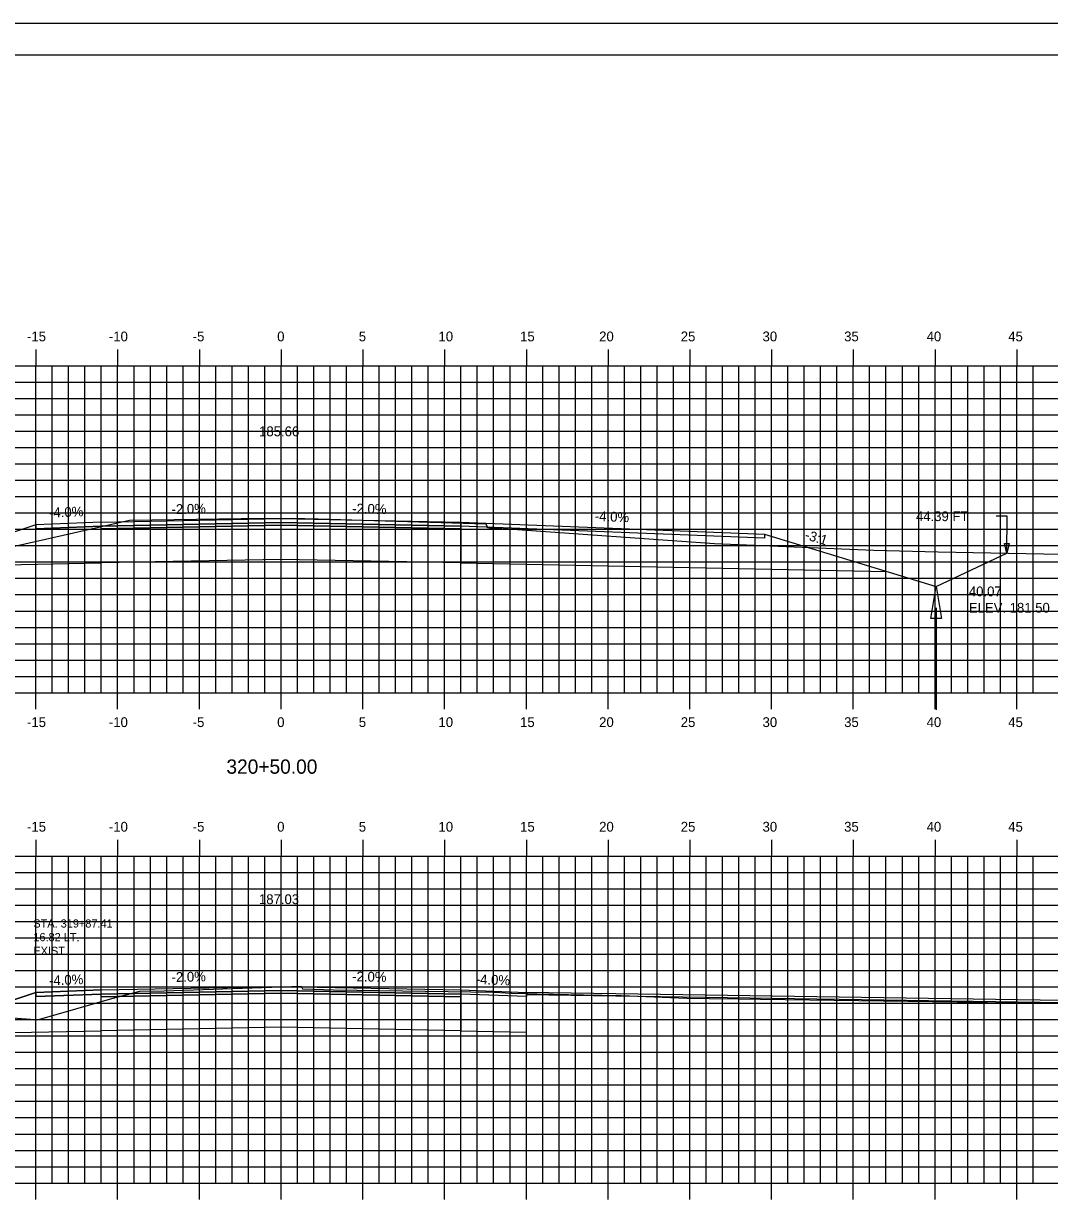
# Model space of a CAD drawing. Extents: x 1139650 to 1139820, y 608981 to 609091.
# Drawn here: x 1139717.5 to 1139780.2, y 609019.1 to 609091.3 of the extents above; entities that cross this region are included whole.
import ezdxf

# ---------------------------------------------------------------- set-up
doc = ezdxf.new("R2010")
doc.units = 0
for name, color, linetype in [('ANNOTATION', 7, 'Continuous'), ('BORDER', 7, 'Continuous'), ('D_Drainage_Ditch_Line', 7, 'Continuous'), ('D_Roadway_Centerline', 7, 'Continuous'), ('D_Roadway_Centerline_Text', 7, 'Continuous'), ('D_Roadway_Edge_Shoulder', 7, 'Continuous'), ('D_Roadway_Edge_TW', 7, 'Continuous'), ('D_Roadway_Pavement', 7, 'Continuous'), ('D_Roadway_SubGrade', 7, 'Continuous'), ('D_Text_Monospaced', 7, 'Continuous'), ('D_Text_Standard', 7, 'Continuous'), ('H_V ANNOTATION', 7, 'Continuous'), ('MAJOR', 7, 'Continuous'), ('MINOR', 7, 'Continuous'), ('PLOT BOUNDARY', 7, 'Continuous'), ('S_Roadway_Centerline', 7, 'Continuous')]:
    doc.layers.add(name, color=color, linetype=linetype)

msp = doc.modelspace()

# ---------------------------------------------------------------- linework, layer by layer
msp.add_lwpolyline([(1139697.827, 609032.096), (1139699.077, 609031.975), (1139700.327, 609031.71), (1139701.577, 609031.3), (1139702.827, 609030.747), (1139707.494, 609028.414), (1139710.494, 609029.414), (1139718.217, 609031.989), (1139718.218, 609031.989), (1139722.218, 609032.149), (1139733.218, 609032.369), (1139744.218, 609032.149), (1139748.218, 609031.989)])
at = {"layer": 'BORDER'}
msp.add_lwpolyline([(1139658.219, 608984.335), (1139818.219, 608984.335), (1139818.219, 609089.335), (1139658.219, 609089.335)], close=True, dxfattribs=at)
at = {"layer": 'D_Drainage_Ditch_Line'}
msp.add_line((1139773.288, 609055.523), (1139773.288, 609049.279), dxfattribs=at)
msp.add_lwpolyline([(1139773.616, 609054.867), (1139772.96, 609054.867), (1139773.288, 609056.835)], close=True, dxfattribs=at)
at = {"layer": 'D_Roadway_Edge_Shoulder'}
for points in [[(1139722.218, 609060.776), (1139718.218, 609060.616), (1139718.218, 609060.366), (1139722.218, 609060.526)], [(1139744.218, 609060.776), (1139762.791, 609060.033), (1139762.791, 609059.783), (1139744.218, 609060.526)], [(1139722.218, 609032.149), (1139718.218, 609031.989), (1139718.218, 609031.739), (1139722.218, 609031.899)], [(1139744.218, 609032.149), (1139748.218, 609031.989), (1139748.218, 609031.739), (1139744.218, 609031.899)]]:
    msp.add_lwpolyline(points, close=True, dxfattribs=at)
for points in [[(1139797.588, 609031.189), (1139790.588, 609031.365), (1139748.218, 609031.989)], [(1139748.218, 609031.989), (1139748.218, 609031.864), (1139790.588, 609031.24), (1139797.588, 609031.064), (1139797.588, 609031.189)]]:
    msp.add_lwpolyline(points, dxfattribs=at)
at = {"layer": 'D_Roadway_Edge_TW'}
for points in [[(1139722.218, 609060.526), (1139722.218, 609060.776), (1139733.218, 609060.996), (1139744.218, 609060.776), (1139744.218, 609060.526), (1139733.218, 609060.746)], [(1139722.218, 609031.899), (1139722.218, 609032.149), (1139733.218, 609032.369), (1139744.218, 609032.149), (1139744.218, 609031.899), (1139733.218, 609032.119)]]:
    msp.add_lwpolyline(points, close=True, dxfattribs=at)
at = {"layer": 'D_Roadway_Pavement'}
for points in [[(1139722.218, 609060.359), (1139722.218, 609060.526), (1139733.218, 609060.746), (1139744.218, 609060.526), (1139744.218, 609060.359), (1139733.218, 609060.579)], [(1139722.218, 609031.732), (1139722.218, 609031.899), (1139733.218, 609032.119), (1139744.218, 609031.899), (1139744.218, 609031.732), (1139733.218, 609031.952)]]:
    msp.add_lwpolyline(points, close=True, dxfattribs=at)
at = {"layer": 'D_Roadway_SubGrade'}
for p, q in [((1139762.791, 609060.033), (1139773.288, 609056.835)), ((1139773.288, 609056.835), (1139777.608, 609058.876))]:
    msp.add_line(p, q, dxfattribs=at)
for points in [[(1139722.218, 609060.359), (1139722.218, 609060.526), (1139718.218, 609060.366), (1139718.218, 609060.616), (1139718.217, 609060.616), (1139710.494, 609058.041), (1139722.218, 609058.276)], [(1139722.218, 609058.276), (1139722.218, 609060.359), (1139733.218, 609060.579), (1139744.218, 609060.359), (1139744.218, 609058.276), (1139733.218, 609058.496)], [(1139722.218, 609031.732), (1139722.218, 609031.899), (1139718.218, 609031.739), (1139718.218, 609031.989), (1139718.217, 609031.989), (1139710.494, 609029.414), (1139722.218, 609029.649)], [(1139748.218, 609030.989), (1139748.218, 609031.989), (1139748.218, 609031.989), (1139748.218, 609031.739), (1139744.218, 609031.899), (1139744.218, 609031.732), (1139744.218, 609029.649), (1139748.218, 609029.569)], [(1139722.218, 609029.649), (1139722.218, 609031.732), (1139733.218, 609031.952), (1139744.218, 609031.732), (1139744.218, 609029.649), (1139733.218, 609029.869)]]:
    msp.add_lwpolyline(points, close=True, dxfattribs=at)
msp.add_lwpolyline([(1139744.218, 609058.276), (1139754.218, 609058.076), (1139770.269, 609057.755)], dxfattribs=at)
at = {"layer": 'D_Text_Standard'}
msp.add_lwpolyline([(1139777.608, 609058.876), (1139777.629, 609061.135), (1139776.95, 609061.135)], dxfattribs=at)
msp.add_lwpolyline([(1139777.608, 609058.876), (1139777.468, 609059.46), (1139777.759, 609059.457)], close=True, dxfattribs=at)
at = {"layer": 'MAJOR'}
for p, q in [((1139718.218, 609071.337), (1139718.218, 609070.335)), ((1139723.218, 609071.337), (1139723.218, 609070.335)), ((1139728.218, 609071.337), (1139728.218, 609070.335)), ((1139733.218, 609071.337), (1139733.218, 609070.335)), ((1139738.218, 609071.337), (1139738.218, 609070.335)), ((1139743.218, 609071.337), (1139743.218, 609070.335)), ((1139748.218, 609071.337), (1139748.218, 609070.335)), ((1139753.218, 609071.337), (1139753.218, 609070.335)), ((1139758.218, 609071.337), (1139758.218, 609070.335)), ((1139763.218, 609071.337), (1139763.218, 609070.335)), ((1139768.218, 609071.337), (1139768.218, 609070.335)), ((1139773.218, 609071.337), (1139773.218, 609070.335)), ((1139778.218, 609071.337), (1139778.218, 609070.335)), ((1139663.218, 609070.335), (1139803.218, 609070.335)), ((1139663.218, 609070.335), (1139803.218, 609070.335)), ((1139718.218, 609050.335), (1139718.218, 609070.335)), ((1139723.218, 609050.335), (1139723.218, 609070.335)), ((1139728.218, 609050.335), (1139728.218, 609070.335)), ((1139733.218, 609050.335), (1139733.218, 609070.335)), ((1139738.218, 609050.335), (1139738.218, 609070.335)), ((1139743.218, 609050.335), (1139743.218, 609070.335)), ((1139748.218, 609050.335), (1139748.218, 609070.335)), ((1139753.218, 609050.335), (1139753.218, 609070.335)), ((1139758.218, 609050.335), (1139758.218, 609070.335)), ((1139763.218, 609050.335), (1139763.218, 609070.335)), ((1139768.218, 609050.335), (1139768.218, 609070.335)), ((1139773.218, 609050.335), (1139773.218, 609070.335)), ((1139778.218, 609050.335), (1139778.218, 609070.335)), ((1139663.218, 609065.335), (1139803.218, 609065.335)), ((1139663.218, 609060.335), (1139803.218, 609060.335)), ((1139663.218, 609055.335), (1139803.218, 609055.335)), ((1139663.218, 609050.335), (1139803.218, 609050.335)), ((1139663.218, 609050.335), (1139803.218, 609050.335)), ((1139718.218, 609049.333), (1139718.218, 609050.335)), ((1139723.218, 609049.333), (1139723.218, 609050.335)), ((1139728.218, 609049.333), (1139728.218, 609050.335)), ((1139733.218, 609049.333), (1139733.218, 609050.335)), ((1139738.218, 609049.333), (1139738.218, 609050.335)), ((1139743.218, 609049.333), (1139743.218, 609050.335)), ((1139748.218, 609049.333), (1139748.218, 609050.335)), ((1139753.218, 609049.333), (1139753.218, 609050.335)), ((1139758.218, 609049.333), (1139758.218, 609050.335)), ((1139763.218, 609049.333), (1139763.218, 609050.335)), ((1139768.218, 609049.333), (1139768.218, 609050.335)), ((1139773.218, 609049.333), (1139773.218, 609050.335)), ((1139778.218, 609049.333), (1139778.218, 609050.335)), ((1139718.218, 609041.337), (1139718.218, 609040.335)), ((1139723.218, 609041.337), (1139723.218, 609040.335)), ((1139728.218, 609041.337), (1139728.218, 609040.335)), ((1139733.218, 609041.337), (1139733.218, 609040.335)), ((1139738.218, 609041.337), (1139738.218, 609040.335)), ((1139743.218, 609041.337), (1139743.218, 609040.335)), ((1139748.218, 609041.337), (1139748.218, 609040.335)), ((1139753.218, 609041.337), (1139753.218, 609040.335)), ((1139758.218, 609041.337), (1139758.218, 609040.335)), ((1139763.218, 609041.337), (1139763.218, 609040.335)), ((1139768.218, 609041.337), (1139768.218, 609040.335)), ((1139773.218, 609041.337), (1139773.218, 609040.335)), ((1139778.218, 609041.337), (1139778.218, 609040.335)), ((1139663.218, 609040.335), (1139803.218, 609040.335)), ((1139663.218, 609040.335), (1139803.218, 609040.335)), ((1139718.218, 609020.335), (1139718.218, 609040.335)), ((1139723.218, 609020.335), (1139723.218, 609040.335)), ((1139728.218, 609020.335), (1139728.218, 609040.335)), ((1139733.218, 609020.335), (1139733.218, 609040.335)), ((1139738.218, 609020.335), (1139738.218, 609040.335)), ((1139743.218, 609020.335), (1139743.218, 609040.335)), ((1139748.218, 609020.335), (1139748.218, 609040.335)), ((1139753.218, 609020.335), (1139753.218, 609040.335)), ((1139758.218, 609020.335), (1139758.218, 609040.335)), ((1139763.218, 609020.335), (1139763.218, 609040.335)), ((1139768.218, 609020.335), (1139768.218, 609040.335)), ((1139773.218, 609020.335), (1139773.218, 609040.335)), ((1139778.218, 609020.335), (1139778.218, 609040.335)), ((1139663.218, 609035.335), (1139803.218, 609035.335)), ((1139663.218, 609030.335), (1139803.218, 609030.335)), ((1139663.218, 609025.335), (1139803.218, 609025.335)), ((1139663.218, 609020.335), (1139803.218, 609020.335)), ((1139663.218, 609020.335), (1139803.218, 609020.335)), ((1139718.218, 609019.333), (1139718.218, 609020.335)), ((1139723.218, 609019.333), (1139723.218, 609020.335)), ((1139728.218, 609019.333), (1139728.218, 609020.335)), ((1139733.218, 609019.333), (1139733.218, 609020.335)), ((1139738.218, 609019.333), (1139738.218, 609020.335)), ((1139743.218, 609019.333), (1139743.218, 609020.335)), ((1139748.218, 609019.333), (1139748.218, 609020.335)), ((1139753.218, 609019.333), (1139753.218, 609020.335)), ((1139758.218, 609019.333), (1139758.218, 609020.335)), ((1139763.218, 609019.333), (1139763.218, 609020.335)), ((1139768.218, 609019.333), (1139768.218, 609020.335)), ((1139773.218, 609019.333), (1139773.218, 609020.335)), ((1139778.218, 609019.333), (1139778.218, 609020.335))]:
    msp.add_line(p, q, dxfattribs=at)
at = {"layer": 'MINOR'}
for p, q in [((1139719.218, 609050.335), (1139719.218, 609070.335)), ((1139720.218, 609050.335), (1139720.218, 609070.335)), ((1139721.218, 609050.335), (1139721.218, 609070.335)), ((1139722.218, 609050.335), (1139722.218, 609070.335)), ((1139724.218, 609050.335), (1139724.218, 609070.335)), ((1139725.218, 609050.335), (1139725.218, 609070.335)), ((1139726.218, 609050.335), (1139726.218, 609070.335)), ((1139727.218, 609050.335), (1139727.218, 609070.335)), ((1139729.218, 609050.335), (1139729.218, 609070.335)), ((1139730.218, 609050.335), (1139730.218, 609070.335)), ((1139731.218, 609050.335), (1139731.218, 609070.335)), ((1139732.218, 609050.335), (1139732.218, 609070.335)), ((1139734.218, 609050.335), (1139734.218, 609070.335)), ((1139735.218, 609050.335), (1139735.218, 609070.335)), ((1139736.218, 609050.335), (1139736.218, 609070.335)), ((1139737.218, 609050.335), (1139737.218, 609070.335)), ((1139739.218, 609050.335), (1139739.218, 609070.335)), ((1139740.218, 609050.335), (1139740.218, 609070.335)), ((1139741.218, 609050.335), (1139741.218, 609070.335)), ((1139742.218, 609050.335), (1139742.218, 609070.335)), ((1139744.218, 609050.335), (1139744.218, 609070.335)), ((1139745.218, 609050.335), (1139745.218, 609070.335)), ((1139746.218, 609050.335), (1139746.218, 609070.335)), ((1139747.218, 609050.335), (1139747.218, 609070.335)), ((1139749.218, 609050.335), (1139749.218, 609070.335)), ((1139750.218, 609050.335), (1139750.218, 609070.335)), ((1139751.218, 609050.335), (1139751.218, 609070.335)), ((1139752.218, 609050.335), (1139752.218, 609070.335)), ((1139754.218, 609050.335), (1139754.218, 609070.335)), ((1139755.218, 609050.335), (1139755.218, 609070.335)), ((1139756.218, 609050.335), (1139756.218, 609070.335)), ((1139757.218, 609050.335), (1139757.218, 609070.335)), ((1139759.218, 609050.335), (1139759.218, 609070.335)), ((1139760.218, 609050.335), (1139760.218, 609070.335)), ((1139761.218, 609050.335), (1139761.218, 609070.335)), ((1139762.218, 609050.335), (1139762.218, 609070.335)), ((1139764.218, 609050.335), (1139764.218, 609070.335)), ((1139765.218, 609050.335), (1139765.218, 609070.335)), ((1139766.218, 609050.335), (1139766.218, 609070.335)), ((1139767.218, 609050.335), (1139767.218, 609070.335)), ((1139769.218, 609050.335), (1139769.218, 609070.335)), ((1139770.218, 609050.335), (1139770.218, 609070.335)), ((1139771.218, 609050.335), (1139771.218, 609070.335)), ((1139772.218, 609050.335), (1139772.218, 609070.335)), ((1139774.218, 609050.335), (1139774.218, 609070.335)), ((1139775.218, 609050.335), (1139775.218, 609070.335)), ((1139776.218, 609050.335), (1139776.218, 609070.335)), ((1139777.218, 609050.335), (1139777.218, 609070.335)), ((1139779.218, 609050.335), (1139779.218, 609070.335)), ((1139663.218, 609069.335), (1139803.218, 609069.335)), ((1139663.218, 609068.335), (1139803.218, 609068.335)), ((1139663.218, 609067.335), (1139803.218, 609067.335)), ((1139663.218, 609066.335), (1139803.218, 609066.335)), ((1139663.218, 609064.335), (1139803.218, 609064.335)), ((1139663.218, 609063.335), (1139803.218, 609063.335)), ((1139663.218, 609062.335), (1139803.218, 609062.335)), ((1139663.218, 609061.335), (1139803.218, 609061.335)), ((1139663.218, 609059.335), (1139803.218, 609059.335)), ((1139663.218, 609058.335), (1139803.218, 609058.335)), ((1139663.218, 609057.335), (1139803.218, 609057.335)), ((1139663.218, 609056.335), (1139803.218, 609056.335)), ((1139663.218, 609054.335), (1139803.218, 609054.335)), ((1139663.218, 609053.335), (1139803.218, 609053.335)), ((1139663.218, 609052.335), (1139803.218, 609052.335)), ((1139663.218, 609051.335), (1139803.218, 609051.335)), ((1139719.218, 609020.335), (1139719.218, 609040.335)), ((1139720.218, 609020.335), (1139720.218, 609040.335)), ((1139721.218, 609020.335), (1139721.218, 609040.335)), ((1139722.218, 609020.335), (1139722.218, 609040.335)), ((1139724.218, 609020.335), (1139724.218, 609040.335)), ((1139725.218, 609020.335), (1139725.218, 609040.335)), ((1139726.218, 609020.335), (1139726.218, 609040.335)), ((1139727.218, 609020.335), (1139727.218, 609040.335)), ((1139729.218, 609020.335), (1139729.218, 609040.335)), ((1139730.218, 609020.335), (1139730.218, 609040.335)), ((1139731.218, 609020.335), (1139731.218, 609040.335)), ((1139732.218, 609020.335), (1139732.218, 609040.335)), ((1139734.218, 609020.335), (1139734.218, 609040.335)), ((1139735.218, 609020.335), (1139735.218, 609040.335)), ((1139736.218, 609020.335), (1139736.218, 609040.335)), ((1139737.218, 609020.335), (1139737.218, 609040.335)), ((1139739.218, 609020.335), (1139739.218, 609040.335)), ((1139740.218, 609020.335), (1139740.218, 609040.335)), ((1139741.218, 609020.335), (1139741.218, 609040.335)), ((1139742.218, 609020.335), (1139742.218, 609040.335)), ((1139744.218, 609020.335), (1139744.218, 609040.335)), ((1139745.218, 609020.335), (1139745.218, 609040.335)), ((1139746.218, 609020.335), (1139746.218, 609040.335)), ((1139747.218, 609020.335), (1139747.218, 609040.335)), ((1139749.218, 609020.335), (1139749.218, 609040.335)), ((1139750.218, 609020.335), (1139750.218, 609040.335)), ((1139751.218, 609020.335), (1139751.218, 609040.335)), ((1139752.218, 609020.335), (1139752.218, 609040.335)), ((1139754.218, 609020.335), (1139754.218, 609040.335)), ((1139755.218, 609020.335), (1139755.218, 609040.335)), ((1139756.218, 609020.335), (1139756.218, 609040.335)), ((1139757.218, 609020.335), (1139757.218, 609040.335)), ((1139759.218, 609020.335), (1139759.218, 609040.335)), ((1139760.218, 609020.335), (1139760.218, 609040.335)), ((1139761.218, 609020.335), (1139761.218, 609040.335)), ((1139762.218, 609020.335), (1139762.218, 609040.335)), ((1139764.218, 609020.335), (1139764.218, 609040.335)), ((1139765.218, 609020.335), (1139765.218, 609040.335)), ((1139766.218, 609020.335), (1139766.218, 609040.335)), ((1139767.218, 609020.335), (1139767.218, 609040.335)), ((1139769.218, 609020.335), (1139769.218, 609040.335)), ((1139770.218, 609020.335), (1139770.218, 609040.335)), ((1139771.218, 609020.335), (1139771.218, 609040.335)), ((1139772.218, 609020.335), (1139772.218, 609040.335)), ((1139774.218, 609020.335), (1139774.218, 609040.335)), ((1139775.218, 609020.335), (1139775.218, 609040.335)), ((1139776.218, 609020.335), (1139776.218, 609040.335)), ((1139777.218, 609020.335), (1139777.218, 609040.335)), ((1139779.218, 609020.335), (1139779.218, 609040.335)), ((1139663.218, 609039.335), (1139803.218, 609039.335)), ((1139663.218, 609038.335), (1139803.218, 609038.335)), ((1139663.218, 609037.335), (1139803.218, 609037.335)), ((1139663.218, 609036.335), (1139803.218, 609036.335)), ((1139663.218, 609034.335), (1139803.218, 609034.335)), ((1139663.218, 609033.335), (1139803.218, 609033.335)), ((1139663.218, 609032.335), (1139803.218, 609032.335)), ((1139663.218, 609031.335), (1139803.218, 609031.335)), ((1139663.218, 609029.335), (1139803.218, 609029.335)), ((1139663.218, 609028.335), (1139803.218, 609028.335)), ((1139663.218, 609027.335), (1139803.218, 609027.335)), ((1139663.218, 609026.335), (1139803.218, 609026.335)), ((1139663.218, 609024.335), (1139803.218, 609024.335)), ((1139663.218, 609023.335), (1139803.218, 609023.335)), ((1139663.218, 609022.335), (1139803.218, 609022.335)), ((1139663.218, 609021.335), (1139803.218, 609021.335))]:
    msp.add_line(p, q, dxfattribs=at)
at = {"layer": 'PLOT BOUNDARY'}
msp.add_lwpolyline([(1139650.125, 608981.276), (1139820.125, 608981.276), (1139820.125, 609091.276), (1139650.125, 609091.276)], close=True, dxfattribs=at)
at = {"layer": 'S_Roadway_Centerline'}
for points in [[(1139715.804, 609059.061), (1139723.951, 609060.903), (1139730.764, 609060.998), (1139733.874, 609061.023), (1139735.482, 609060.984), (1139745.746, 609060.665), (1139745.849, 609060.452), (1139745.954, 609060.43), (1139747.1, 609060.358), (1139759.719, 609059.456), (1139769.483, 609059.052), (1139773.402, 609058.957), (1139794.906, 609058.546), (1139803.218, 609058.444)], [(1139715.7, 609030.526), (1139718.142, 609030.349), (1139718.452, 609030.361), (1139722.864, 609031.617), (1139724.571, 609032.081), (1139726.072, 609032.102), (1139734.44, 609032.382), (1139734.524, 609032.22), (1139736.438, 609032.16), (1139746.219, 609032.007), (1139747.3, 609031.947), (1139748.3, 609031.924), (1139748.884, 609031.91), (1139749.885, 609031.889), (1139751.711, 609031.852), (1139754.01, 609031.808), (1139758.043, 609031.653), (1139759.397, 609031.632), (1139761.21, 609031.604), (1139762.545, 609031.584), (1139774.563, 609031.412), (1139776.429, 609031.385), (1139779.966, 609031.34), (1139782.848, 609031.308)]]:
    msp.add_lwpolyline(points, dxfattribs=at)

# ---------------------------------------------------------------- texts
at = {"layer": 'ANNOTATION'}
for s, rotation, p in [('-4.0%', 2.29061, (1139719.034, 609061.049)), ('-2.0%', 1.14576, (1139726.521, 609061.262)), ('-2.0%', 358.85424, (1139737.561, 609061.309)), ('-4.0%', 357.70939, (1139752.401, 609060.849)), ('-3:1', 343.14552, (1139765.212, 609059.744)), ('-4.0%', 2.29061, (1139719.034, 609032.422)), ('-2.0%', 1.14576, (1139726.521, 609032.635)), ('-2.0%', 358.85424, (1139737.561, 609032.682)), ('-4.0%', 357.70939, (1139745.114, 609032.514))]:
    msp.add_text(s, height=0.6, rotation=rotation, dxfattribs=at).set_placement(p)
at = {"layer": 'D_Roadway_Centerline'}
for s, p in [('C', (1139733.213, 609060.996)), ('L', (1139733.218, 609060.989)), ('C', (1139733.213, 609032.369)), ('L', (1139733.218, 609032.361))]:
    msp.add_text(s, height=0.0146, dxfattribs=at).set_placement(p)
at = {"layer": 'D_Roadway_Centerline_Text'}
for s, p in [('185.66', (1139731.87, 609066.028)), ('187.03', (1139731.862, 609037.401))]:
    msp.add_text(s, height=0.6, dxfattribs=at).set_placement(p)
at = {"layer": 'D_Text_Monospaced'}
for s, height, p in [('STA. 319+87.41', 0.49998, (1139718.061, 609035.966)), ('16.82 LT.', 0.5, (1139718.061, 609035.132)), ('EXIST. ', 0.5, (1139718.061, 609034.292))]:
    msp.add_text(s, height=height, dxfattribs=at).set_placement(p)
at = {"layer": 'D_Text_Standard'}
for s, p in [('44.39 FT', (1139772.052, 609060.835)), ('40.07', (1139775.288, 609056.235)), ('ELEV. 181.50', (1139775.288, 609055.233))]:
    msp.add_text(s, height=0.6, dxfattribs=at).set_placement(p)
at = {"layer": 'H_V ANNOTATION'}
for s, height, p in [('-15', 0.6, (1139717.675, 609071.835)), ('-10', 0.6, (1139722.683, 609071.835)), ('-5', 0.6, (1139727.809, 609071.835)), ('0', 0.6, (1139732.977, 609071.835)), ('5', 0.6, (1139737.969, 609071.835)), ('10', 0.6, (1139742.844, 609071.835)), ('15', 0.6, (1139747.836, 609071.835)), ('20', 0.6, (1139752.672, 609071.835)), ('25', 0.6, (1139757.664, 609071.835)), ('30', 0.6, (1139762.667, 609071.835)), ('35', 0.6, (1139767.659, 609071.835)), ('40', 0.6, (1139772.704, 609071.835)), ('45', 0.6, (1139777.696, 609071.835)), ('-15', 0.6, (1139717.675, 609048.235)), ('-10', 0.6, (1139722.683, 609048.235)), ('-5', 0.6, (1139727.809, 609048.235)), ('0', 0.6, (1139732.977, 609048.235)), ('5', 0.6, (1139737.969, 609048.235)), ('10', 0.6, (1139742.844, 609048.235)), ('15', 0.6, (1139747.836, 609048.235)), ('20', 0.6, (1139752.672, 609048.235)), ('25', 0.6, (1139757.664, 609048.235)), ('30', 0.6, (1139762.667, 609048.235)), ('35', 0.6, (1139767.659, 609048.235)), ('40', 0.6, (1139772.704, 609048.235)), ('45', 0.6, (1139777.696, 609048.235)), ('320+50.00', 0.875, (1139729.871, 609045.378)), ('-15', 0.6, (1139717.675, 609041.835)), ('-10', 0.6, (1139722.683, 609041.835)), ('-5', 0.6, (1139727.809, 609041.835)), ('0', 0.6, (1139732.977, 609041.835)), ('5', 0.6, (1139737.969, 609041.835)), ('10', 0.6, (1139742.844, 609041.835)), ('15', 0.6, (1139747.836, 609041.835)), ('20', 0.6, (1139752.672, 609041.835)), ('25', 0.6, (1139757.664, 609041.835)), ('30', 0.6, (1139762.667, 609041.835)), ('35', 0.6, (1139767.659, 609041.835)), ('40', 0.6, (1139772.704, 609041.835)), ('45', 0.6, (1139777.696, 609041.835))]:
    msp.add_text(s, height=height, dxfattribs=at).set_placement(p)
at = {"layer": 'S_Roadway_Centerline'}
for s, p in [('C', (1139733.869, 609061.023)), ('L', (1139733.874, 609061.016)), ('C', (1139734.435, 609032.382)), ('L', (1139734.44, 609032.374))]:
    msp.add_text(s, height=0.0146, dxfattribs=at).set_placement(p)

doc.saveas('drawing.dxf')
